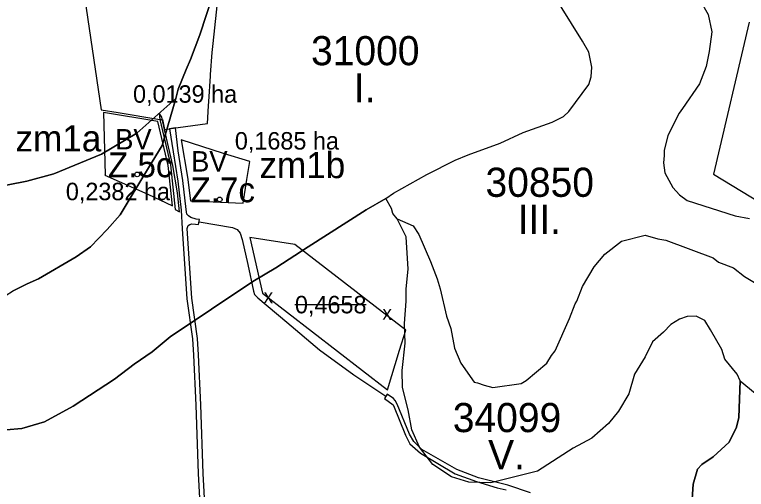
# Model space of a CAD drawing. Extents: x -555509 to -553014, y -1186753 to -1182560.
# Drawn here: x -554443 to -553941, y -1185751 to -1185425 of the extents above; entities that cross this region are included whole.
import ezdxf

# ---------------------------------------------------------------- set-up
doc = ezdxf.new("R2010")
doc.units = 0
for name, color, linetype in [('LEG_1_ZCU', 7, 'Continuous'), ('LEG_6_ZPF', 7, 'Continuous'), ('Level 29', 7, 'Continuous'), ('Level 4', 7, 'Continuous'), ('Level 46', 7, 'Continuous'), ('Level 52', 7, 'Continuous'), ('Level 58', 7, 'Continuous'), ('pěší_tr', 7, 'Continuous'), ('ram_HLV', 7, 'Continuous'), ('ZABOR_ke_zruseni', 7, 'Continuous'), ('ZM_rozpiska_VYROK', 7, 'Continuous'), ('ZPF_I_TR_OCHRANY', 7, 'Continuous'), ('ZPF_zabor', 7, 'Continuous')]:
    doc.layers.add(name, color=color, linetype=linetype)

msp = doc.modelspace()

# ---------------------------------------------------------------- linework, layer by layer
at = {"layer": 'LEG_6_ZPF'}
for p, q in [((-554341.5, -1185515.13), (-554332.19, -1185482.88)), ((-554383.06, -1185521), (-554415.75, -1185534.63)), ((-554415.75, -1185534.63), (-554434.38, -1185539.63)), ((-554370.38, -1185562.63), (-554364, -1185552.38)), ((-554241.44, -1185584.63), (-554263.5, -1185599)), ((-554263.5, -1185599), (-554279.19, -1185608.38)), ((-554279.19, -1185608.38), (-554336, -1185646.5)), ((-554437.75, -1185709.25), (-554448.38, -1185710.13))]:
    msp.add_line(p, q, dxfattribs=at)
for points in [[(-554332.19, -1185482.88), (-554358.88, -1185506.63), (-554383.06, -1185521)], [(-554364, -1185552.38), (-554350.88, -1185530.38), (-554341.5, -1185515.13)], [(-554434.38, -1185539.63), (-554532.31, -1185558.75), (-554542.06, -1185560.5)], [(-554188.06, -1185551.5), (-554201.62, -1185559.13), (-554241.44, -1185584.63)], [(-554180.44, -1185565.5), (-554183.38, -1185561.75), (-554184.25, -1185558.38), (-554188.06, -1185551.5)], [(-554433.94, -1185610), (-554426.31, -1185606.62), (-554400.44, -1185591.38), (-554390.69, -1185584.63), (-554379.25, -1185572.75), (-554370.38, -1185562.63)], [(-553945.12, -1185676.63), (-553947.25, -1185672), (-553955.69, -1185661.75), (-553957.81, -1185655), (-553965.44, -1185641.5), (-553969.25, -1185635.12), (-553975.19, -1185632.13), (-553981.56, -1185632.5), (-553986.62, -1185634.25), (-553992.56, -1185638), (-553997.69, -1185643.12), (-554005.31, -1185649.88), (-554010.38, -1185660.13), (-554017.62, -1185672), (-554021.44, -1185685.5), (-554028.62, -1185697.38), (-554035.44, -1185705.88), (-554046.88, -1185716), (-554059.56, -1185722.88), (-554084.19, -1185738.5), (-554116, -1185746.63), (-554131.25, -1185746.13), (-554143.12, -1185742.38), (-554155.81, -1185733.88), (-554165.12, -1185722), (-554170.25, -1185710.13), (-554172.75, -1185696.5), (-554176.62, -1185681.25), (-554177, -1185669.38), (-554174.88, -1185650.75), (-554175.31, -1185637.25), (-554174.06, -1185621.88), (-554174.06, -1185613.5), (-554172.75, -1185599.88), (-554174.06, -1185577.88), (-554180.44, -1185565.5)], [(-554470, -1185627.88), (-554453, -1185620.63), (-554444.12, -1185615.13), (-554433.94, -1185610)], [(-554336, -1185646.5), (-554348.31, -1185656.75), (-554360.62, -1185665.13), (-554374.19, -1185675.38), (-554402.56, -1185694), (-554422.06, -1185704.63), (-554437.75, -1185709.25)], [(-554049.38, -1185821.63), (-554027.38, -1185814.88), (-554008.69, -1185808.88), (-554003.19, -1185803.38), (-553996.38, -1185796.62), (-553985.81, -1185784.75), (-553981.56, -1185778), (-553978.62, -1185767.75), (-553977.31, -1185747.38), (-553974.38, -1185737.25), (-553971.38, -1185733.88), (-553963.75, -1185728.75), (-553952.75, -1185718.62), (-553947.62, -1185708.38), (-553945.94, -1185701.63), (-553945.12, -1185676.63)]]:
    msp.add_lwpolyline(points, dxfattribs=at)
at = {"layer": 'Level 29'}
for points in [[(-554332.19, -1185482.88), (-554330.5, -1185476.5), (-554325, -1185463), (-554322, -1185456.12), (-554315.69, -1185439.25), (-554306.31, -1185410.38), (-554302.12, -1185402.75), (-554300.81, -1185400.25), (-554299.12, -1185398.5), (-554295.31, -1185391.75), (-554286, -1185378.13), (-554268.19, -1185357.75), (-554253.75, -1185344.25), (-554249.94, -1185339.12), (-554247, -1185335.75), (-554244.44, -1185330.62), (-554244, -1185323.88), (-554246.56, -1185309.88)], [(-554031.62, -1185349.38), (-554032.44, -1185357.38), (-554031.19, -1185362.5), (-554024.81, -1185376), (-554020.12, -1185381.13), (-553988.75, -1185401.5), (-553972.69, -1185415), (-553967.12, -1185425.25), (-553964.62, -1185437.13), (-553966.31, -1185450.63), (-553968.44, -1185460.88), (-553973.06, -1185472.75), (-553984.56, -1185489.63), (-553987.06, -1185493), (-553994.69, -1185508.25), (-553997.25, -1185518.5), (-553997.25, -1185521.88), (-553997.69, -1185527), (-553996.81, -1185533.75), (-553991.31, -1185543.88), (-553986.62, -1185549), (-553981.56, -1185552.88), (-553948.5, -1185563.38), (-553938.75, -1185565.12)], [(-554188.06, -1185551.5), (-554182.94, -1185547.75), (-554160.06, -1185535), (-554140.56, -1185525.25), (-554131.62, -1185521.5), (-554109.62, -1185513.38), (-554093.94, -1185506.25), (-554074, -1185499), (-554066.38, -1185495.13), (-554062.56, -1185491.75), (-554049, -1185473.12), (-554047.31, -1185468), (-554046.88, -1185461.25), (-554049, -1185451.13), (-554053.25, -1185443.5), (-554074.81, -1185408.63), (-554079.94, -1185400.25), (-554093.94, -1185382.38)], [(-554668.81, -1185666), (-554639.12, -1185660.5), (-554632.38, -1185658), (-554627.31, -1185654.12), (-554620.06, -1185645.62), (-554612.44, -1185633.75), (-554606.94, -1185620.25), (-554605.25, -1185610), (-554600.56, -1185598.25), (-554592.94, -1185586.38), (-554589.56, -1185582.88), (-554586.19, -1185579.13), (-554572.19, -1185570.25), (-554542.06, -1185560.5), (-554532.31, -1185558.75), (-554434.38, -1185539.63), (-554415.75, -1185534.63), (-554383.06, -1185521), (-554358.88, -1185506.63), (-554332.19, -1185482.88)], [(-554332.19, -1185482.88), (-554341.5, -1185515.13), (-554350.88, -1185530.38), (-554364, -1185552.38), (-554370.38, -1185562.63), (-554379.25, -1185572.75), (-554390.69, -1185584.63), (-554400.44, -1185591.38), (-554426.31, -1185606.62), (-554433.94, -1185610), (-554444.12, -1185615.13)], [(-554448.38, -1185710.13), (-554437.75, -1185709.25), (-554422.06, -1185704.63), (-554402.56, -1185694), (-554374.19, -1185675.38), (-554360.62, -1185665.13), (-554348.31, -1185656.75), (-554336, -1185646.5), (-554279.19, -1185608.38), (-554263.5, -1185599), (-554241.44, -1185584.63), (-554201.62, -1185559.13), (-554188.06, -1185551.5)], [(-554180.44, -1185565.5), (-554183.38, -1185561.75), (-554184.25, -1185558.38), (-554188.06, -1185551.5)], [(-553945.12, -1185676.63), (-553947.25, -1185672), (-553955.69, -1185661.75), (-553957.81, -1185655), (-553965.44, -1185641.5), (-553969.25, -1185635.12), (-553975.19, -1185632.13), (-553981.56, -1185632.5), (-553986.62, -1185634.25), (-553992.56, -1185638), (-553997.69, -1185643.12), (-554005.31, -1185649.88), (-554010.38, -1185660.13), (-554017.62, -1185672), (-554021.44, -1185685.5), (-554028.62, -1185697.38), (-554035.44, -1185705.88), (-554046.88, -1185716), (-554059.56, -1185722.88), (-554084.19, -1185738.5), (-554116, -1185746.63), (-554131.25, -1185746.13), (-554143.12, -1185742.38), (-554155.81, -1185733.88), (-554165.12, -1185722), (-554170.25, -1185710.13), (-554172.75, -1185696.5), (-554176.62, -1185681.25), (-554177, -1185669.38), (-554174.88, -1185650.75), (-554175.31, -1185637.25), (-554174.06, -1185621.88), (-554174.06, -1185613.5), (-554172.75, -1185599.88), (-554174.06, -1185577.88), (-554180.44, -1185565.5)], [(-554180.44, -1185565.5), (-554169.38, -1185570.25), (-554165.56, -1185576.13), (-554157.5, -1185594.75), (-554152.88, -1185606.62), (-554150.75, -1185613.5), (-554146.5, -1185632.13), (-554143.5, -1185640.63), (-554141, -1185654.12), (-554136.75, -1185664.38), (-554127.44, -1185677.5), (-554125.31, -1185677.88), (-554120.62, -1185679.62), (-554114.69, -1185681.25), (-554095.19, -1185678.38), (-554091.81, -1185676.25), (-554077.81, -1185664.38), (-554074.44, -1185659.25), (-554071.88, -1185655.88), (-554062.12, -1185633.75), (-554058.31, -1185623.63), (-554057.06, -1185621.88), (-554053.25, -1185611.75), (-554045.19, -1185598.25), (-554037.94, -1185589.75), (-554026.5, -1185580.75), (-554010.38, -1185576.63), (-554001.5, -1185579.13), (-553996, -1185580), (-553963.75, -1185592.25), (-553959.94, -1185595.25), (-553949.75, -1185599), (-553942.12, -1185605), (-553916.69, -1185620.25)], [(-553945.12, -1185676.63), (-553934.94, -1185685.13), (-553931.12, -1185686.38), (-553929.44, -1185687.62), (-553923.88, -1185687.62), (-553914.56, -1185684.63), (-553910.75, -1185682.12), (-553903.12, -1185673.63), (-553893.81, -1185666.5), (-553876.88, -1185661), (-553863.69, -1185661.75), (-553846.75, -1185678.38), (-553829.38, -1185690.25)], [(-553945.12, -1185676.63), (-553945.94, -1185701.63), (-553947.62, -1185708.38), (-553952.75, -1185718.62), (-553963.75, -1185728.75), (-553971.38, -1185733.88), (-553974.38, -1185737.25), (-553977.31, -1185747.38), (-553978.62, -1185767.75), (-553981.56, -1185778), (-553985.81, -1185784.75), (-553996.38, -1185796.62), (-554003.19, -1185803.38), (-554008.69, -1185808.88), (-554027.38, -1185814.88), (-554049.38, -1185821.63)]]:
    msp.add_lwpolyline(points, dxfattribs=at)
at = {"layer": 'Level 4'}
for centre in [(-554358.57, -1185534.95), (-554358.57, -1185534.95), (-554302.04, -1185552.12)]:
    msp.add_circle(centre, 1.64, dxfattribs=at)
at = {"layer": 'Level 52'}
msp.add_line((-554343.14, -1185497.2), (-554341.31, -1185497.3), dxfattribs=at)
for points in [[(-554341.31, -1185497.3), (-554339.9, -1185504.2), (-554330.54, -1185502.81), (-554310.42, -1185499.99), (-554309.65, -1185487.97), (-554309.44, -1185484.8), (-554308.32, -1185467.44), (-554308.26, -1185466.47), (-554307.28, -1185451.33), (-554306.61, -1185445.15), (-554298.85, -1185373.97)], [(-554399.87, -1185378.78), (-554383.32, -1185490.61), (-554371.71, -1185492.51), (-554343.14, -1185497.2)], [(-553938.9, -1185430.55), (-553963.43, -1185534.75), (-553931.3, -1185554.25)]]:
    msp.add_lwpolyline(points, dxfattribs=at)
at = {"layer": 'Level 58'}
for p, q in [((-554341.66, -1185495.58), (-554343.59, -1185493)), ((-554343.59, -1185493), (-554343.14, -1185497.2)), ((-554339.9, -1185504.2), (-554341.66, -1185495.58)), ((-554343.14, -1185497.2), (-554335.87, -1185528.47)), ((-554334.07, -1185528.75), (-554339.9, -1185504.2)), ((-554335.87, -1185528.47), (-554332.6, -1185559.09)), ((-554330.85, -1185547.51), (-554334.07, -1185528.75)), ((-554329.61, -1185560.51), (-554330.85, -1185547.51)), ((-554332.6, -1185559.09), (-554329.61, -1185560.51))]:
    msp.add_line(p, q, dxfattribs=at)
at = {"layer": 'pěší_tr'}
for points in [[(-554311.49, -1185773.9), (-554313.39, -1185740.09), (-554314.85, -1185693.03), (-554316.58, -1185658.74), (-554317.27, -1185647.45), (-554321.16, -1185619.87), (-554324.26, -1185571.96), (-554323.93, -1185570.73), (-554323.55, -1185569.98), (-554322.55, -1185569.24), (-554321.17, -1185568.9), (-554318.67, -1185569.01), (-554316.47, -1185569.29), (-554315.92, -1185565.83), (-554318.15, -1185565.55), (-554321.86, -1185564.58), (-554323.5, -1185563.46), (-554324.49, -1185562.21), (-554325.04, -1185558.99), (-554327.2, -1185539.01), (-554330.49, -1185518.85), (-554332.23, -1185503.06), (-554336.36, -1185503.67), (-554333.94, -1185519.42), (-554330.67, -1185539.48), (-554328.52, -1185559.36), (-554327.75, -1185572.19), (-554324.64, -1185620.23), (-554320.76, -1185647.8), (-554320.07, -1185658.94), (-554318.35, -1185693.17), (-554316.88, -1185740.24), (-554314.98, -1185774.09)], [(-554316.2, -1185567.56), (-554293.14, -1185571.26), (-554290.09, -1185572.67), (-554288.1, -1185575.27), (-554286.66, -1185579.52), (-554282.76, -1185596.78), (-554278.92, -1185615.07), (-554278.24, -1185617.27), (-554275.97, -1185619.59), (-554256.04, -1185636.24), (-554233.5, -1185655.29), (-554210.14, -1185672.35), (-554188.15, -1185687.15)], [(-554088.87, -1185753.41), (-554104.45, -1185748.13), (-554124.46, -1185743.03), (-554139.42, -1185737.51), (-554163.41, -1185723.6), (-554168.98, -1185718.23), (-554171.94, -1185713.23), (-554180.43, -1185692.53), (-554181.67, -1185690.14), (-554182.94, -1185688.81), (-554187.17, -1185685.7), (-554189.12, -1185688.6), (-554183.1, -1185693.05), (-554182.94, -1185693.44), (-554174.52, -1185713.8), (-554171.66, -1185719.81), (-554164.23, -1185726.28), (-554140.61, -1185740.42), (-554126.03, -1185745.61), (-554111.78, -1185749.93), (-554105.57, -1185751.45)]]:
    msp.add_lwpolyline(points, dxfattribs=at)
at = {"layer": 'ZABOR_ke_zruseni'}
for p, q in [((-554174.43, -1185641.89), (-554250.48, -1185583.07)), ((-554250.44, -1185624.27), (-554201.58, -1185624.27))]:
    msp.add_line(p, q, dxfattribs=at)
for points in [[(-554250.48, -1185583.07), (-554281.41, -1185578.27), (-554272.65, -1185616.49), (-554187.01, -1185682.72)], [(-554187.01, -1185682.72), (-554178.64, -1185655.55), (-554174.43, -1185641.89)]]:
    msp.add_lwpolyline(points, dxfattribs=at)
at = {"layer": 'ZPF_I_TR_OCHRANY'}
for p, q in [((-554315.69, -1185439.25), (-554322, -1185456.12)), ((-554322, -1185456.12), (-554325, -1185463))]:
    msp.add_line(p, q, dxfattribs=at)
for points in [[(-554332.19, -1185482.88), (-554330.5, -1185476.5), (-554325, -1185463), (-554322, -1185456.12), (-554315.69, -1185439.25), (-554306.31, -1185410.38), (-554302.12, -1185402.75), (-554300.81, -1185400.25), (-554299.12, -1185398.5), (-554295.31, -1185391.75), (-554286, -1185378.13), (-554268.19, -1185357.75), (-554253.75, -1185344.25), (-554249.94, -1185339.12), (-554247, -1185335.75), (-554244.44, -1185330.62), (-554244, -1185323.88), (-554246.56, -1185309.88)], [(-554031.62, -1185349.38), (-554032.44, -1185357.38), (-554031.19, -1185362.5), (-554024.81, -1185376), (-554020.12, -1185381.13), (-553988.75, -1185401.5), (-553972.69, -1185415), (-553967.12, -1185425.25), (-553964.62, -1185437.13), (-553966.31, -1185450.63), (-553968.44, -1185460.88), (-553973.06, -1185472.75), (-553984.56, -1185489.63), (-553987.06, -1185493), (-553994.69, -1185508.25), (-553997.25, -1185518.5), (-553997.25, -1185521.88), (-553997.69, -1185527), (-553996.81, -1185533.75), (-553991.31, -1185543.88), (-553986.62, -1185549), (-553981.56, -1185552.88), (-553948.5, -1185563.38), (-553938.75, -1185565.12)], [(-554188.06, -1185551.5), (-554182.94, -1185547.75), (-554160.06, -1185535), (-554140.56, -1185525.25), (-554131.62, -1185521.5), (-554109.62, -1185513.38), (-554093.94, -1185506.25), (-554074, -1185499), (-554066.38, -1185495.13), (-554062.56, -1185491.75), (-554049, -1185473.12), (-554047.31, -1185468), (-554046.88, -1185461.25), (-554049, -1185451.13), (-554053.25, -1185443.5), (-554074.81, -1185408.63), (-554079.94, -1185400.25), (-554093.94, -1185382.38)], [(-554302.12, -1185402.75), (-554306.31, -1185410.38), (-554315.69, -1185439.25)], [(-554325, -1185463), (-554330.5, -1185476.5), (-554332.19, -1185482.88)], [(-554668.81, -1185666), (-554639.12, -1185660.5), (-554632.38, -1185658), (-554627.31, -1185654.12), (-554620.06, -1185645.62), (-554612.44, -1185633.75), (-554606.94, -1185620.25), (-554605.25, -1185610), (-554600.56, -1185598.25), (-554592.94, -1185586.38), (-554589.56, -1185582.88), (-554586.19, -1185579.13), (-554572.19, -1185570.25), (-554542.06, -1185560.5), (-554532.31, -1185558.75), (-554434.38, -1185539.63), (-554415.75, -1185534.63), (-554383.06, -1185521), (-554358.88, -1185506.63), (-554332.19, -1185482.88)], [(-554332.19, -1185482.88), (-554341.5, -1185515.13), (-554350.88, -1185530.38), (-554364, -1185552.38), (-554370.38, -1185562.63), (-554379.25, -1185572.75), (-554390.69, -1185584.63), (-554400.44, -1185591.38), (-554426.31, -1185606.62), (-554433.94, -1185610), (-554444.12, -1185615.13)], [(-554448.38, -1185710.13), (-554437.75, -1185709.25), (-554422.06, -1185704.63), (-554402.56, -1185694), (-554374.19, -1185675.38), (-554360.62, -1185665.13), (-554348.31, -1185656.75), (-554336, -1185646.5), (-554279.19, -1185608.38), (-554263.5, -1185599), (-554241.44, -1185584.63), (-554201.62, -1185559.13), (-554188.06, -1185551.5)]]:
    msp.add_lwpolyline(points, dxfattribs=at)
at = {"layer": 'ZPF_zabor'}
for points in [[(-554381.77, -1185492.38), (-554380.56, -1185535.28), (-554380.68, -1185535.54), (-554351.34, -1185548.53), (-554334.37, -1185556.59), (-554337.36, -1185528.72), (-554344.38, -1185498.51)], [(-554299.46, -1185520.57), (-554328.37, -1185511.19), (-554324.06, -1185536.87), (-554322.03, -1185553.05), (-554285.95, -1185554.55), (-554283.35, -1185538.48), (-554281.33, -1185525.97)]]:
    msp.add_lwpolyline(points, close=True, dxfattribs=at)

# ---------------------------------------------------------------- texts
at = {"layer": 'LEG_1_ZCU'}
for s, p in [('0,1685 ha', (-554291.64, -1185517.89)), ('0,2382 ha', (-554407.53, -1185552.64))]:
    msp.add_text(s, height=12, dxfattribs=at).set_placement(p)
at = {"layer": 'Level 29'}
for s, p in [('31000', (-554239.38, -1185460.01)), ('I.', (-554210.07, -1185485.46)), ('30850', (-554119.74, -1185550.33)), ('III.', (-554097.71, -1185575.78)), ('34099', (-554142.18, -1185711.78)), ('V.', (-554117.96, -1185737.24))]:
    msp.add_text(s, height=20, dxfattribs=at).set_placement(p)
at = {"layer": 'Level 46'}
for s, p in [('Z.5c', (-554378.59, -1185536.89)), ('Z.7c', (-554322.06, -1185554.05))]:
    msp.add_text(s, height=17, dxfattribs=at).set_placement(p)
at = {"layer": 'Level 58'}
msp.add_text('0,0139 ha', height=12, dxfattribs=at).set_placement((-554361.45, -1185485.75))
at = {"layer": 'ram_HLV'}
for p in [(-554373.66, -1185517.79), (-554321.61, -1185532.97)]:
    msp.add_text('BV', height=14, dxfattribs=at).set_placement(p)
at = {"layer": 'ZABOR_ke_zruseni'}
for p in [(-554271.93, -1185623.24), (-554190.48, -1185634.68)]:
    msp.add_text('x', height=9.63, rotation=359.2857, dxfattribs=at).set_placement(p)
msp.add_text('0,4658', height=12, dxfattribs=at).set_placement((-554250.44, -1185630.27))
at = {"layer": 'ZM_rozpiska_VYROK'}
for s, p in [('zm1a', (-554442.07, -1185519.16)), ('zm1b', (-554274.78, -1185537.49))]:
    msp.add_text(s, height=18, dxfattribs=at).set_placement(p)

doc.saveas('drawing.dxf')
